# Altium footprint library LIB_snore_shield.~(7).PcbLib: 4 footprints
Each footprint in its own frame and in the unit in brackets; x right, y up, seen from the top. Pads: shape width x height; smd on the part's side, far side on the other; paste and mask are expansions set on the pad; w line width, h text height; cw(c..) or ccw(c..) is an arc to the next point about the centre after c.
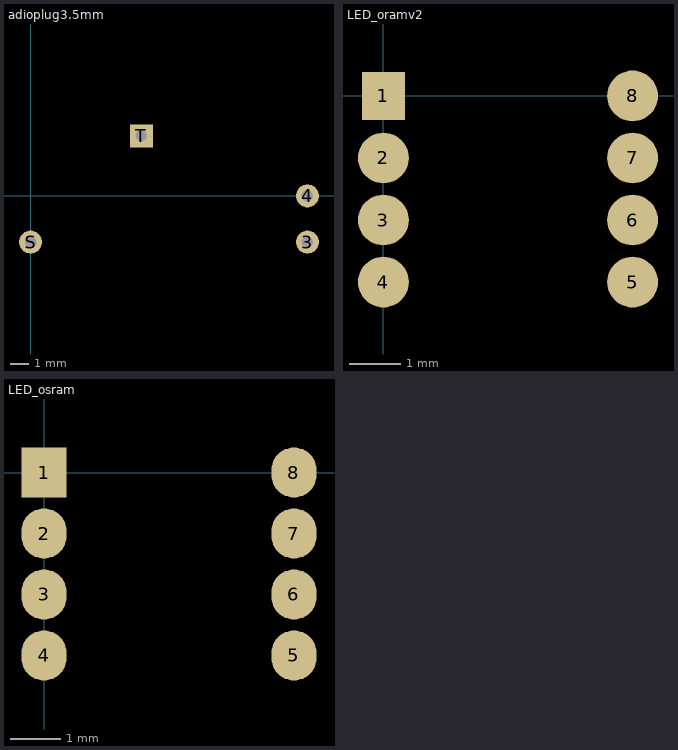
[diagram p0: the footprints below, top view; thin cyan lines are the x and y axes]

## adioplug3.5mm [mil]
pads (4):
  round 50 / inner oval 100x50 / far side round 50 hole 25: 3(600,-100) 4(600,0) S(0,-100)
  rect 50x50 / inner rect 100x50 / far side rect 50x50 hole 25: T(240,130)

## LED_oramv2 [mm]
pads (8):
  rect 0.85x0.95 smd: 1(0,0)
  round 1 smd: 2(0,-1.22) 3(0,-2.44) 4(0,-3.66) 5(4.9,-3.66) 6(4.9,-2.44) 7(4.9,-1.22) 8(4.9,0)

## LED_osram [mm]
pads (8):
  rect 0.9x1 smd: 1(0,0)
  oval 0.9x1 smd: 2(0,-1.22) 3(0,-2.44) 4(0,-3.66) 5(5,-3.66) 6(5,-2.44) 7(5,-1.22) 8(5,0)

## SMD [mm]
